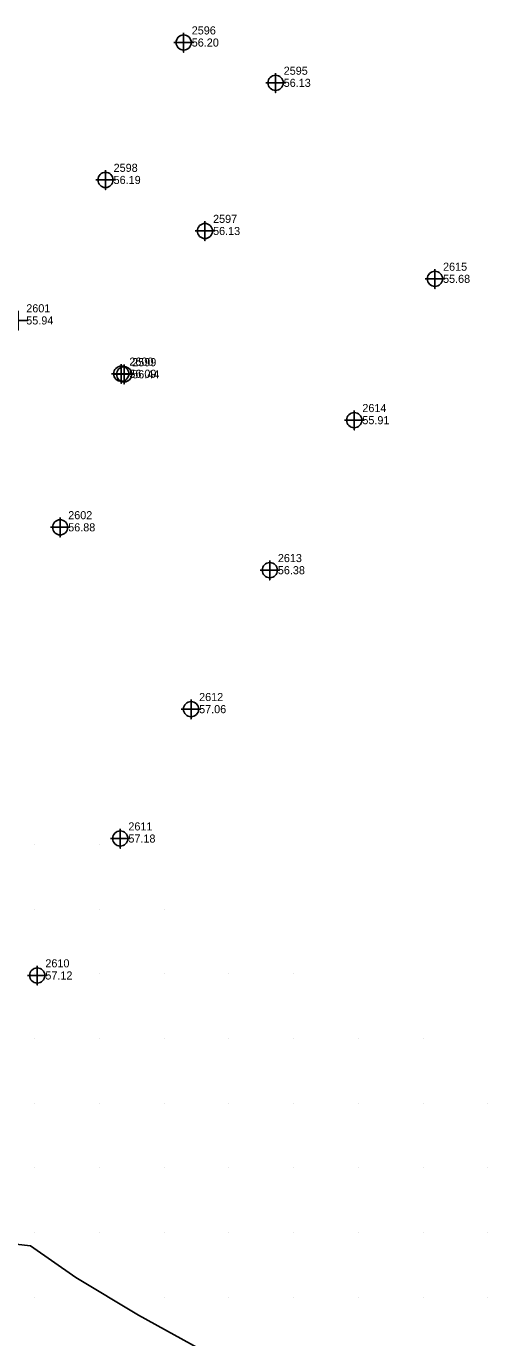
# Model space of a CAD drawing. Extents: x 2062781 to 2066835, y 358981 to 366501.
# Drawn here: x 2066017 to 2066159.6, y 364636.2 to 365041.6 of the extents above; entities that cross this region are included whole.
import ezdxf

# ---------------------------------------------------------------- set-up
doc = ezdxf.new("R2010")
doc.units = 0
for name, color, linetype in [('Exist DTM Regular Point CELL', 7, 'Continuous'), ('Exist DTM Regular Point Cogo Elevation', 7, 'Continuous'), ('Exist DTM Regular Point Cogo Number', 7, 'Continuous'), ('PH Exist DTM Breakline', 7, 'Continuous'), ('PH Exist DTM Point', 7, 'Continuous')]:
    doc.layers.add(name, color=color, linetype=linetype)

msp = doc.modelspace()

# ---------------------------------------------------------------- linework, layer by layer
at = {"layer": 'Exist DTM Regular Point CELL'}
for points in [[(2066065.6, 365039.52), (2066065.6, 365033.52), (2066065.6, 365036.52), (2066068.6, 365036.52), (2066062.6, 365036.52)], [(2066094.01, 365027.06), (2066094.01, 365021.06), (2066094.01, 365024.06), (2066097.01, 365024.06), (2066091.01, 365024.06)], [(2066041.46, 364997.05), (2066041.46, 364991.05), (2066041.46, 364994.05), (2066044.46, 364994.05), (2066038.46, 364994.05)], [(2066072.19, 364981.27), (2066072.19, 364975.27), (2066072.19, 364978.27), (2066075.19, 364978.27), (2066069.19, 364978.27)], [(2066143.25, 364966.48), (2066143.25, 364960.48), (2066143.25, 364963.48), (2066146.25, 364963.48), (2066140.25, 364963.48)], [(2066014.47, 364953.63), (2066014.47, 364947.63), (2066014.47, 364950.63), (2066017.47, 364950.63), (2066011.47, 364950.63)], [(2066046.32, 364937.15), (2066046.32, 364931.15), (2066046.32, 364934.15), (2066049.32, 364934.15), (2066043.32, 364934.15)], [(2066047.22, 364936.97), (2066047.22, 364930.97), (2066047.22, 364933.97), (2066050.22, 364933.97), (2066044.22, 364933.97)], [(2066118.32, 364922.8), (2066118.32, 364916.8), (2066118.32, 364919.8), (2066121.32, 364919.8), (2066115.32, 364919.8)], [(2066027.43, 364889.68), (2066027.43, 364883.68), (2066027.43, 364886.68), (2066030.43, 364886.68), (2066024.43, 364886.68)], [(2066092.21, 364876.43), (2066092.21, 364870.43), (2066092.21, 364873.43), (2066095.21, 364873.43), (2066089.21, 364873.43)], [(2066067.88, 364833.48), (2066067.88, 364827.48), (2066067.88, 364830.48), (2066070.88, 364830.48), (2066064.88, 364830.48)], [(2066046.02, 364793.49), (2066046.02, 364787.49), (2066046.02, 364790.49), (2066049.02, 364790.49), (2066043.02, 364790.49)], [(2066020.37, 364751.17), (2066020.37, 364745.17), (2066020.37, 364748.17), (2066023.37, 364748.17), (2066017.37, 364748.17)]]:
    msp.add_lwpolyline(points, dxfattribs=at)
for centre in [(2066065.6, 365036.52), (2066094.01, 365024.06), (2066041.46, 364994.05), (2066072.19, 364978.27), (2066143.25, 364963.48), (2066046.32, 364934.15), (2066047.22, 364933.97), (2066118.32, 364919.8), (2066027.43, 364886.68), (2066092.21, 364873.43), (2066067.88, 364830.48), (2066046.02, 364790.49), (2066020.37, 364748.17)]:
    msp.add_circle(centre, 2.34, dxfattribs=at)
at = {"layer": 'PH Exist DTM Breakline'}
msp.add_lwpolyline([(2066156.46, 364583.64), (2066145.51, 364589.68), (2066126.72, 364600.54), (2066112.61, 364608.32), (2066093.08, 364619.74), (2066073.68, 364631.01), (2066051.66, 364643.15), (2066032.25, 364654.82), (2066018.3, 364664.64), (2065990.15, 364667.81)], dxfattribs=at)
at = {"layer": 'PH Exist DTM Point'}
for p, q in [((2066019.57, 364788.66), (2066019.57, 364788.66)), ((2066039.57, 364788.66), (2066039.57, 364788.66)), ((2066019.57, 364768.66), (2066019.57, 364768.66)), ((2066039.57, 364768.66), (2066039.57, 364768.66)), ((2066059.57, 364768.66), (2066059.57, 364768.66)), ((2066019.57, 364748.66), (2066019.57, 364748.66)), ((2066039.57, 364748.66), (2066039.57, 364748.66)), ((2066059.57, 364748.66), (2066059.57, 364748.66)), ((2066079.57, 364748.66), (2066079.57, 364748.66)), ((2066099.57, 364748.66), (2066099.57, 364748.66)), ((2066019.57, 364728.66), (2066019.57, 364728.66)), ((2066039.57, 364728.66), (2066039.57, 364728.66)), ((2066059.57, 364728.66), (2066059.57, 364728.66)), ((2066079.57, 364728.66), (2066079.57, 364728.66)), ((2066099.57, 364728.66), (2066099.57, 364728.66)), ((2066119.57, 364728.66), (2066119.57, 364728.66)), ((2066139.57, 364728.66), (2066139.57, 364728.66)), ((2066019.57, 364708.66), (2066019.57, 364708.66)), ((2066039.57, 364708.66), (2066039.57, 364708.66)), ((2066059.57, 364708.66), (2066059.57, 364708.66)), ((2066079.57, 364708.66), (2066079.57, 364708.66)), ((2066099.57, 364708.66), (2066099.57, 364708.66)), ((2066119.57, 364708.66), (2066119.57, 364708.66)), ((2066139.57, 364708.66), (2066139.57, 364708.66)), ((2066159.57, 364708.66), (2066159.57, 364708.66)), ((2066019.57, 364688.66), (2066019.57, 364688.66)), ((2066039.57, 364688.66), (2066039.57, 364688.66)), ((2066059.57, 364688.66), (2066059.57, 364688.66)), ((2066079.57, 364688.66), (2066079.57, 364688.66)), ((2066099.57, 364688.66), (2066099.57, 364688.66)), ((2066119.57, 364688.66), (2066119.57, 364688.66)), ((2066139.57, 364688.66), (2066139.57, 364688.66)), ((2066159.57, 364688.66), (2066159.57, 364688.66)), ((2066019.57, 364668.66), (2066019.57, 364668.66)), ((2066039.57, 364668.66), (2066039.57, 364668.66)), ((2066059.57, 364668.66), (2066059.57, 364668.66)), ((2066079.57, 364668.66), (2066079.57, 364668.66)), ((2066099.57, 364668.66), (2066099.57, 364668.66)), ((2066119.57, 364668.66), (2066119.57, 364668.66)), ((2066139.57, 364668.66), (2066139.57, 364668.66)), ((2066159.57, 364668.66), (2066159.57, 364668.66)), ((2066019.57, 364648.66), (2066019.57, 364648.66)), ((2066059.57, 364648.66), (2066059.57, 364648.66)), ((2066079.57, 364648.66), (2066079.57, 364648.66)), ((2066099.57, 364648.66), (2066099.57, 364648.66)), ((2066119.57, 364648.66), (2066119.57, 364648.66)), ((2066139.57, 364648.66), (2066139.57, 364648.66)), ((2066159.57, 364648.66), (2066159.57, 364648.66))]:
    msp.add_line(p, q, dxfattribs=at)

# ---------------------------------------------------------------- texts
at = {"layer": 'Exist DTM Regular Point Cogo Elevation'}
for s, p in [('56.20', (2066068.1, 365035.27)), ('56.13', (2066096.51, 365022.81)), ('56.19', (2066043.96, 364992.8)), ('56.13', (2066074.69, 364977.02)), ('55.68', (2066145.75, 364962.23)), ('55.94', (2066016.97, 364949.38)), ('56.09', (2066048.82, 364932.9)), ('56.44', (2066049.72, 364932.72)), ('55.91', (2066120.82, 364918.55)), ('56.88', (2066029.93, 364885.43)), ('56.38', (2066094.71, 364872.18)), ('57.06', (2066070.38, 364829.23)), ('57.18', (2066048.52, 364789.24)), ('57.12', (2066022.87, 364746.92))]:
    msp.add_text(s, height=2.5, dxfattribs=at).set_placement(p)
at = {"layer": 'Exist DTM Regular Point Cogo Number'}
for s, p in [('2596', (2066068.1, 365039.02)), ('2595', (2066096.51, 365026.56)), ('2598', (2066043.96, 364996.55)), ('2597', (2066074.69, 364980.77)), ('2615', (2066145.75, 364965.98)), ('2601', (2066016.97, 364953.13)), ('2600', (2066048.82, 364936.65)), ('2599', (2066049.72, 364936.47)), ('2614', (2066120.82, 364922.3)), ('2602', (2066029.93, 364889.18)), ('2613', (2066094.71, 364875.93)), ('2612', (2066070.38, 364832.98)), ('2611', (2066048.52, 364792.99)), ('2610', (2066022.87, 364750.67))]:
    msp.add_text(s, height=2.5, dxfattribs=at).set_placement(p)

doc.saveas('drawing.dxf')
